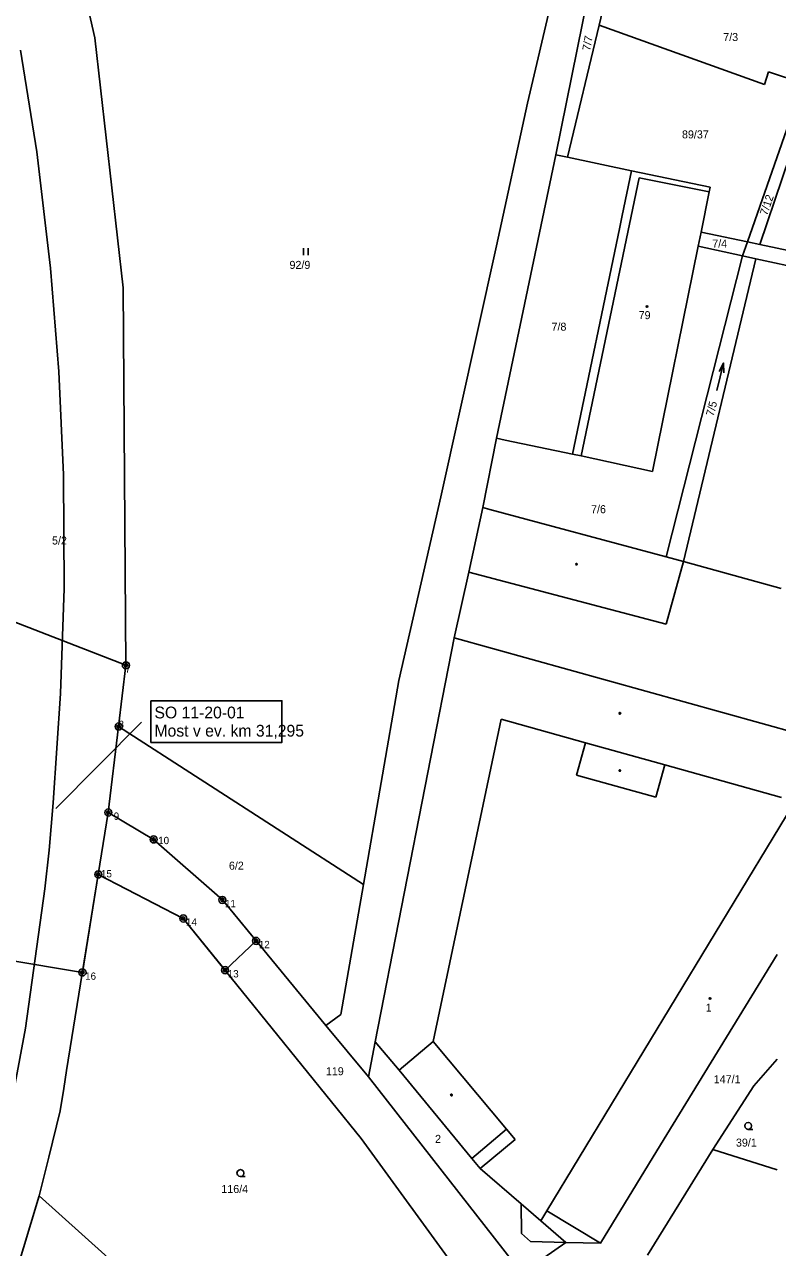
# Model space of a CAD drawing. Extents: x -752343 to -750336, y -1035826 to -1033329.
# Drawn here: x -751691.8 to -751531.8, y -1034430.3 to -1034170.4 of the extents above; entities that cross this region are included whole.
import ezdxf

# ---------------------------------------------------------------- set-up
doc = ezdxf.new("R2010")
doc.units = 0
for name, color, linetype in [('26 - dočasné zábory', 7, 'Continuous'), ('26 - obvod_stavby', 7, 'Continuous'), ('body', 7, 'Continuous'), ('cisla', 7, 'Continuous'), ('Default', 7, 'Continuous'), ('KN_HRANICE', 7, 'Continuous'), ('KN_KULTURY', 7, 'Continuous'), ('KN_PARCELY', 7, 'Continuous'), ('KN_SLUCKY', 7, 'Continuous'), ('SO-Bubliny', 7, 'Continuous'), ('Vrstva 1', 7, 'Continuous')]:
    doc.layers.add(name, color=color, linetype=linetype)

# ---------------------------------------------------------------- blocks, each defined once
blk = doc.blocks.new('304')
at = {"layer": 'Default'}
blk.add_lwpolyline([(0, 0), (-0.38, 0.1), (-0.65, 0.37), (-0.75, 0.74), (-0.65, 1.11), (-0.38, 1.38), (-0.01, 1.48), (0.36, 1.38), (0.63, 1.11), (0.73, 0.73), (0.63, 0.35), (0.36, 0.08), (-0.02, -0.02), (0.98, -0.02)], dxfattribs=at)
blk = doc.blocks.new('306')
at = {"layer": 'Default'}
for p, q in [((-0.5, 1.5), (-0.5, 0)), ((0.5, 0), (0.5, 1.5))]:
    blk.add_line(p, q, dxfattribs=at)
blk = doc.blocks.new('802')
at = {"layer": 'Default'}
blk.add_line((-3, 0), (3, 0), dxfattribs=at)
blk.add_lwpolyline([(1, 0.5), (3, 0), (1, -0.5)], dxfattribs=at)
blk = doc.blocks.new('402')
at = {"layer": 'Default'}
blk.add_lwpolyline([(0.09, 0.15), (0.18, 0), (0.09, -0.15), (-0.09, -0.15), (-0.18, 0), (-0.09, 0.15), (0.09, 0.15)], dxfattribs=at)

msp = doc.modelspace()

# ---------------------------------------------------------------- linework, layer by layer
at = {"layer": '26 - dočasné zábory'}
msp.add_lwpolyline([(-751676.11, -1034351.03), (-751673.98, -1034337.87), (-751664.36, -1034343.6), (-751649.76, -1034356.45), (-751642.58, -1034365.15), (-751649.18, -1034371.37), (-751658.05, -1034360.39), (-751676.11, -1034351.03), (-751673.98, -1034337.87)], dxfattribs=at)
at = {"layer": '26 - obvod_stavby'}
msp.add_lwpolyline([(-751658.05, -1034360.39), (-751649.18, -1034371.37), (-751642.58, -1034365.15), (-751649.76, -1034356.45), (-751664.36, -1034343.6), (-751673.98, -1034337.87), (-751671.8, -1034319.6), (-751670.25, -1034306.59), (-751694.33, -1034297.19), (-751698.5, -1034328.11), (-751731.85, -1034309.62), (-751737.58, -1034319.86), (-751704.51, -1034338.37), (-751712.13, -1034366.43), (-751679.47, -1034371.86), (-751676.11, -1034351.03), (-751658.05, -1034360.39)], dxfattribs=at)
at = {"layer": 'body'}
for p, q in [((-751670.25, -1034306.59), (-751670.25, -1034306.59)), ((-751671.8, -1034319.6), (-751671.8, -1034319.6)), ((-751673.98, -1034337.87), (-751673.98, -1034337.87)), ((-751664.36, -1034343.6), (-751664.36, -1034343.6)), ((-751676.11, -1034351.03), (-751676.11, -1034351.03)), ((-751649.76, -1034356.45), (-751649.76, -1034356.45)), ((-751658.05, -1034360.39), (-751658.05, -1034360.39)), ((-751642.58, -1034365.15), (-751642.58, -1034365.15)), ((-751679.48, -1034371.86), (-751679.48, -1034371.86)), ((-751649.18, -1034371.37), (-751649.18, -1034371.37))]:
    msp.add_line(p, q, dxfattribs=at)
for centre, radius in [((-751670.25, -1034306.59), 0.75), ((-751670.25, -1034306.59), 0.35), ((-751671.8, -1034319.6), 0.75), ((-751671.8, -1034319.6), 0.35), ((-751673.98, -1034337.87), 0.75), ((-751673.98, -1034337.87), 0.35), ((-751664.36, -1034343.6), 0.75), ((-751664.36, -1034343.6), 0.35), ((-751676.11, -1034351.03), 0.75), ((-751676.11, -1034351.03), 0.35), ((-751649.76, -1034356.45), 0.75), ((-751649.76, -1034356.45), 0.35), ((-751658.05, -1034360.39), 0.75), ((-751658.05, -1034360.39), 0.35), ((-751642.58, -1034365.15), 0.75), ((-751642.58, -1034365.15), 0.35), ((-751679.47, -1034371.86), 0.75), ((-751649.18, -1034371.37), 0.75), ((-751649.18, -1034371.37), 0.35), ((-751679.47, -1034371.86), 0.35)]:
    msp.add_circle(centre, radius, dxfattribs=at)
at = {"layer": 'KN_HRANICE'}
for p, q in [((-751691.23, -1034108.8), (-751676.86, -1034173.28)), ((-751569.32, -1034150.96), (-751578.92, -1034198.1)), ((-751584.95, -1034187.15), (-751577.59, -1034155.94)), ((-751568.08, -1034163.6), (-751569.74, -1034170.56)), ((-751569.74, -1034170.56), (-751576.42, -1034198.63)), ((-751569.74, -1034170.56), (-751534.55, -1034183.21)), ((-751676.86, -1034173.28), (-751670.81, -1034226.35)), ((-751534.55, -1034183.21), (-751533.71, -1034180.48)), ((-751533.71, -1034180.48), (-751526.41, -1034182.89)), ((-751591.5, -1034217.44), (-751584.95, -1034187.15)), ((-751528.26, -1034188.18), (-751538.23, -1034216.63)), ((-751535.54, -1034217.19), (-751526.08, -1034189.11)), ((-751591.53, -1034258.36), (-751578.92, -1034198.1)), ((-751576.42, -1034198.63), (-751578.92, -1034198.1)), ((-751562.81, -1034201.5), (-751576.42, -1034198.63)), ((-751564.8, -1034211.03), (-751562.81, -1034201.5)), ((-751546.11, -1034205.02), (-751562.81, -1034201.5)), ((-751548.04, -1034214.56), (-751546.31, -1034206.01)), ((-751546.31, -1034206.01), (-751546.11, -1034205.02)), ((-751564.8, -1034211.03), (-751565.4, -1034213.88)), ((-751575.38, -1034261.73), (-751565.4, -1034213.88)), ((-751548.04, -1034214.56), (-751548.64, -1034217.53)), ((-751538.23, -1034216.63), (-751548.04, -1034214.56)), ((-751603.35, -1034270.82), (-751591.5, -1034217.44)), ((-751558.35, -1034265.41), (-751548.64, -1034217.53)), ((-751548.64, -1034217.53), (-751539.29, -1034219.58)), ((-751539.29, -1034219.58), (-751538.23, -1034216.63)), ((-751538.23, -1034216.63), (-751535.54, -1034217.19)), ((-751469.19, -1034231.17), (-751535.54, -1034217.19)), ((-751555.46, -1034283.51), (-751539.29, -1034219.58)), ((-751536.39, -1034220.21), (-751551.76, -1034284.51)), ((-751539.29, -1034219.58), (-751536.39, -1034220.21)), ((-751536.39, -1034220.21), (-751472.26, -1034234.2)), ((-751670.81, -1034226.35), (-751670.25, -1034306.59)), ((-751591.53, -1034258.36), (-751594.4, -1034273.07)), ((-751591.53, -1034258.36), (-751589.67, -1034258.75)), ((-751589.67, -1034258.75), (-751575.38, -1034261.73)), ((-751575.38, -1034261.73), (-751573.54, -1034262.11)), ((-751573.54, -1034262.11), (-751558.35, -1034265.41)), ((-751612.23, -1034309.8), (-751603.35, -1034270.82)), ((-751597.39, -1034286.83), (-751594.4, -1034273.07)), ((-751594.4, -1034273.07), (-751592.92, -1034273.47)), ((-751555.46, -1034283.51), (-751592.92, -1034273.47)), ((-751551.76, -1034284.51), (-751555.46, -1034283.51)), ((-751551.76, -1034284.51), (-751531.02, -1034290.29)), ((-751600.51, -1034300.74), (-751597.39, -1034286.83)), ((-751600.51, -1034300.74), (-751617.27, -1034386.59)), ((-751671.8, -1034319.6), (-751670.25, -1034306.59)), ((-751619.79, -1034353.2), (-751612.23, -1034309.8)), ((-751673.98, -1034337.87), (-751671.8, -1034319.6)), ((-751671.8, -1034319.6), (-751619.79, -1034353.2)), ((-751676.11, -1034351.03), (-751673.98, -1034337.87)), ((-751673.98, -1034337.87), (-751664.36, -1034343.6)), ((-751664.36, -1034343.6), (-751649.76, -1034356.45)), ((-751682.84, -1034392.69), (-751676.11, -1034351.03)), ((-751676.11, -1034351.03), (-751658.05, -1034360.39)), ((-751624.6, -1034380.78), (-751619.79, -1034353.2)), ((-751649.76, -1034356.45), (-751627.74, -1034383.13)), ((-751658.05, -1034360.39), (-751620.28, -1034407.14)), ((-751556.65, -1034408.47), (-751531.86, -1034368.06)), ((-751624.6, -1034380.78), (-751627.74, -1034383.13)), ((-751627.74, -1034383.13), (-751618.73, -1034394.05)), ((-751617.27, -1034386.59), (-751618.73, -1034394.05)), ((-751612.21, -1034392.61), (-751617.27, -1034386.59)), ((-751531.86, -1034390.28), (-751536.85, -1034395.95)), ((-751683.46, -1034396.55), (-751682.84, -1034392.69)), ((-751618.73, -1034394.05), (-751586.12, -1034435.76)), ((-751596.76, -1034411.38), (-751612.21, -1034392.61)), ((-751684.22, -1034401.25), (-751683.46, -1034396.55)), ((-751536.85, -1034395.95), (-751545.55, -1034409.5)), ((-751686.63, -1034411.12), (-751684.22, -1034401.25)), ((-751620.28, -1034407.14), (-751594.74, -1034442.18)), ((-751569.4, -1034429.41), (-751556.65, -1034408.47)), ((-751545.55, -1034409.5), (-751559.45, -1034431.95)), ((-751545.55, -1034409.5), (-751531.86, -1034413.8)), ((-751688.64, -1034419.35), (-751686.63, -1034411.12)), ((-751594.98, -1034413.54), (-751596.76, -1034411.38)), ((-751586.29, -1034421.03), (-751594.98, -1034413.54)), ((-751700.27, -1034457.61), (-751688.64, -1034419.35)), ((-751688.64, -1034419.35), (-751607.43, -1034492.1)), ((-751582.1, -1034424.64), (-751586.29, -1034421.03)), ((-751576.79, -1034429.21), (-751582.1, -1034424.64)), ((-751576.79, -1034429.21), (-751586.12, -1034435.76)), ((-751569.4, -1034429.41), (-751576.79, -1034429.21))]:
    msp.add_line(p, q, dxfattribs=at)
at = {"layer": 'KN_SLUCKY'}
for p, q in [((-751561.19, -1034203.03), (-751573.54, -1034262.11)), ((-751546.31, -1034206.01), (-751561.19, -1034203.03)), ((-751551.76, -1034284.51), (-751555.47, -1034297.82)), ((-751597.39, -1034286.83), (-751555.47, -1034297.82)), ((-751600.51, -1034300.74), (-751527.21, -1034321.17)), ((-751604.96, -1034386.54), (-751590.54, -1034318.07)), ((-751572.59, -1034323.07), (-751590.54, -1034318.07)), ((-751520.57, -1034323.02), (-751580.81, -1034422.5)), ((-751574.51, -1034329.93), (-751572.59, -1034323.07)), ((-751555.76, -1034327.75), (-751572.59, -1034323.07)), ((-751555.76, -1034327.75), (-751557.68, -1034334.62)), ((-751530.96, -1034334.65), (-751555.76, -1034327.75)), ((-751557.68, -1034334.62), (-751574.51, -1034329.93)), ((-751604.96, -1034386.54), (-751612.21, -1034392.61)), ((-751604.96, -1034386.54), (-751589.36, -1034405.19)), ((-751596.76, -1034411.38), (-751589.36, -1034405.19)), ((-751587.56, -1034407.34), (-751594.98, -1034413.54)), ((-751589.36, -1034405.19), (-751587.56, -1034407.34)), ((-751586.22, -1034427.34), (-751586.29, -1034421.03)), ((-751580.81, -1034422.5), (-751582.1, -1034424.64)), ((-751580.81, -1034422.5), (-751569.4, -1034429.41)), ((-751584.28, -1034429.01), (-751586.22, -1034427.34)), ((-751576.79, -1034429.21), (-751584.28, -1034429.01))]:
    msp.add_line(p, q, dxfattribs=at)
at = {"layer": 'SO-Bubliny'}
msp.add_line((-751666.94, -1034318.7), (-751685.12, -1034337.04), dxfattribs=at)
msp.add_lwpolyline([(-751664.95, -1034314.14), (-751637.11, -1034314.14), (-751637.11, -1034322.98), (-751664.95, -1034322.98)], close=True, dxfattribs=at)
at = {"layer": 'Vrstva 1'}
msp.add_lwpolyline([(-751695.18, -1034403.05), (-751691.59, -1034383.71), (-751687.45, -1034354.07), (-751686.58, -1034345.84), (-751685.68, -1034335.8), (-751684.12, -1034312.56), (-751683.36, -1034290.24), (-751683.5, -1034266.15), (-751684.5, -1034244.18), (-751686.28, -1034222.24), (-751689.19, -1034197.49), (-751692.67, -1034175.89)], dxfattribs=at)

# ---------------------------------------------------------------- block references
at = {"layer": 'KN_KULTURY'}
for name, p in [('306', (-751632.04, -1034219.44)), ('402', (-751559.56, -1034230.36)), ('402', (-751574.51, -1034285.11)), ('402', (-751565.31, -1034316.8)), ('402', (-751565.33, -1034328.97)), ('402', (-751546.15, -1034377.37)), ('402', (-751601.08, -1034397.9)), ('304', (-751538.04, -1034405.2)), ('304', (-751645.91, -1034415.22))]:
    msp.add_blockref(name, p, dxfattribs=at)
at = {"layer": 'KN_KULTURY', "rotation": 76.08879499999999}
msp.add_blockref('802', (-751543.98, -1034245.27), dxfattribs=at)

# ---------------------------------------------------------------- texts
at = {"layer": 'cisla'}
for s, p in [('  7', (-751671.53, -1034308.14)), ('  8', (-751672.96, -1034319.93)), ('  9', (-751673.98, -1034339.42)), (' 10', (-751663.96, -1034344.59)), (' 15', (-751676.11, -1034351.65)), (' 11', (-751649.76, -1034358)), (' 14', (-751658.05, -1034361.94)), (' 12', (-751642.58, -1034366.7)), (' 16', (-751679.48, -1034373.41)), (' 13', (-751649.18, -1034372.92))]:
    msp.add_text(s, height=1.552, dxfattribs=at).set_placement(p)
at = {"layer": 'KN_PARCELY'}
for s, rotation, p in [('7/7', 79.412, (-751571.64, -1034176.1)), ('7/12', 70.875, (-751534.03, -1034211.13)), ('7/5', 75.172, (-751545.42, -1034253.78))]:
    msp.add_text(s, height=1.7, rotation=rotation, dxfattribs=at).set_placement(p)
for s, p in [('7/3', (-751543.35, -1034173.94)), ('89/37', (-751552.11, -1034194.63)), ('7/4', (-751545.68, -1034217.82)), ('92/9', (-751635.49, -1034222.36)), ('79', (-751561.32, -1034233.04)), ('7/8', (-751579.83, -1034235.49)), ('7/6', (-751571.43, -1034274.27)), ('5/2', (-751685.94, -1034280.92)), ('6/2', (-751648.36, -1034350.02)), ('1', (-751547.07, -1034380.18)), ('119', (-751627.76, -1034393.7)), ('147/1', (-751545.37, -1034395.39)), ('2', (-751604.57, -1034408.07)), ('39/1', (-751540.65, -1034408.86)), ('116/4', (-751649.97, -1034418.72))]:
    msp.add_text(s, height=1.7, dxfattribs=at).set_placement(p)
at = {"layer": 'SO-Bubliny'}
for s, p in [('SO 11-20-01', (-751664.18, -1034317.87)), ('Most v ev. km 31,295', (-751664.18, -1034321.74))]:
    msp.add_text(s, height=2.5, dxfattribs=at).set_placement(p)

doc.saveas('drawing.dxf')
